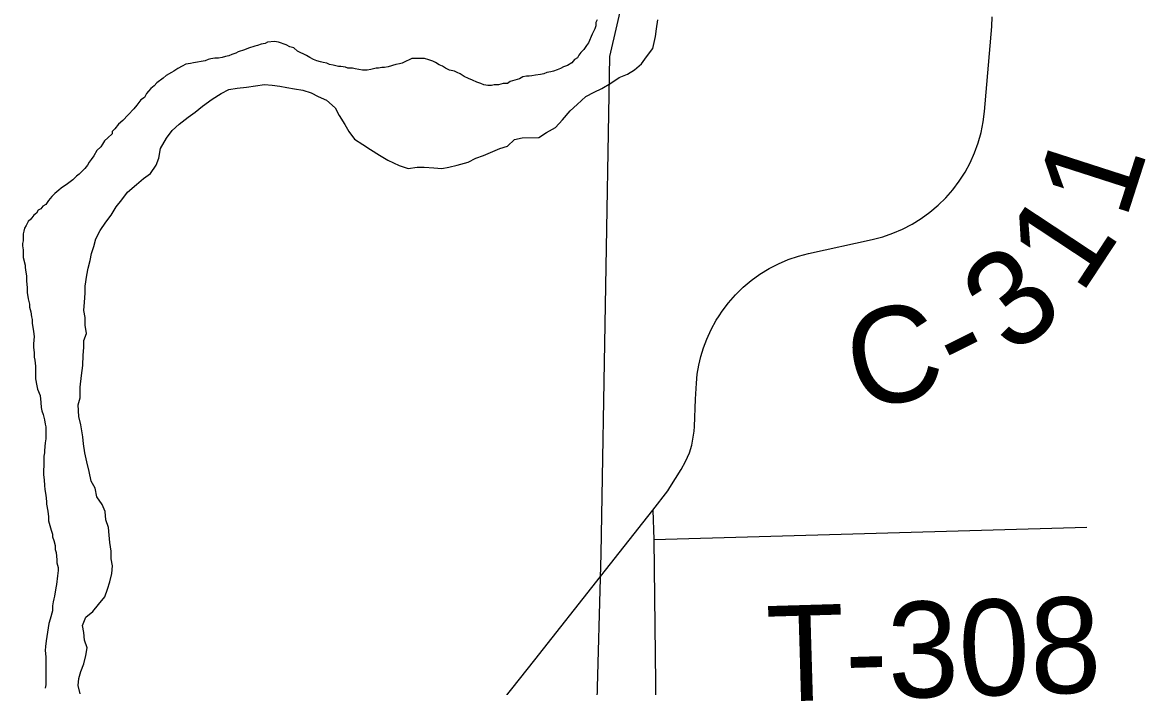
# Model space of a CAD drawing. Extents: x -59 to 82, y -3 to 49.
# Drawn here: x -52.911 to -52.245, y 46.56 to 46.954 of the extents above; entities that cross this region are included whole.
import ezdxf

# ---------------------------------------------------------------- set-up
doc = ezdxf.new("R2010")
doc.units = 0
for name, color, linetype in [('GM_X_Corporation', 7, 'Continuous'), ('GM_X_County_Road', 7, 'Continuous'), ('GM_X_County_Road_Text', 7, 'Continuous'), ('GM_X_Major_River', 7, 'Continuous'), ('GM_X_Township_Road', 7, 'Continuous'), ('GM_X_Township_Road_Text', 7, 'Continuous')]:
    doc.layers.add(name, color=color, linetype=linetype)

msp = doc.modelspace()

# ---------------------------------------------------------------- linework, layer by layer
at = {"layer": 'GM_X_Corporation'}
for p, q in [((-52.56251, 46.93385), (-52.55268, 46.97631)), ((-52.56755, 46.63881), (-52.56251, 46.93385)), ((-52.57812, 46.27168), (-52.56755, 46.63881))]:
    msp.add_line(p, q, dxfattribs=at)
at = {"layer": 'GM_X_County_Road'}
for p, q in [((-52.34011, 46.90124), (-52.33576, 46.95155)), ((-52.33576, 46.95155), (-52.3355, 46.95721)), ((-52.34089, 46.89493), (-52.34011, 46.90124)), ((-52.34214, 46.8887), (-52.34089, 46.89493)), ((-52.34385, 46.88258), (-52.34214, 46.8887)), ((-52.34602, 46.8766), (-52.34385, 46.88258)), ((-52.34862, 46.8708), (-52.34602, 46.8766)), ((-52.35508, 46.85986), (-52.35164, 46.86521)), ((-52.35164, 46.86521), (-52.34862, 46.8708)), ((-52.3589, 46.85478), (-52.35508, 46.85986)), ((-52.36309, 46.85), (-52.3589, 46.85478)), ((-52.37248, 46.84144), (-52.36763, 46.84554)), ((-52.36763, 46.84554), (-52.36309, 46.85)), ((-52.38304, 46.83437), (-52.37763, 46.83771)), ((-52.37763, 46.83771), (-52.37248, 46.84144)), ((-52.39453, 46.82895), (-52.38868, 46.83144)), ((-52.38868, 46.83144), (-52.38304, 46.83437)), ((-52.44447, 46.81695), (-52.4067, 46.82529)), ((-52.4067, 46.82529), (-52.40054, 46.82689)), ((-52.40054, 46.82689), (-52.39453, 46.82895)), ((-52.46238, 46.81085), (-52.45657, 46.81332)), ((-52.45657, 46.81332), (-52.45059, 46.81536)), ((-52.45059, 46.81536), (-52.44447, 46.81695)), ((-52.4785, 46.80095), (-52.47338, 46.80464)), ((-52.47338, 46.80464), (-52.468, 46.80795)), ((-52.468, 46.80795), (-52.46238, 46.81085)), ((-52.48334, 46.79688), (-52.4785, 46.80095)), ((-52.49205, 46.78774), (-52.48786, 46.79247)), ((-52.48786, 46.79247), (-52.48334, 46.79688)), ((-52.49587, 46.78271), (-52.49205, 46.78774)), ((-52.49931, 46.77741), (-52.49759, 46.78006)), ((-52.49759, 46.78006), (-52.49587, 46.78271)), ((-52.50496, 46.76612), (-52.50234, 46.77187)), ((-52.50234, 46.77187), (-52.49931, 46.77741)), ((-52.50685, 46.76109), (-52.50496, 46.76612)), ((-52.50841, 46.75595), (-52.50685, 46.76109)), ((-52.50965, 46.75073), (-52.50841, 46.75595)), ((-52.51113, 46.7401), (-52.51056, 46.74544)), ((-52.51056, 46.74544), (-52.50965, 46.75073)), ((-52.51154, 46.7306), (-52.51113, 46.7401)), ((-52.51215, 46.71433), (-52.51154, 46.7306)), ((-52.51376, 46.70335), (-52.51238, 46.71154)), ((-52.51238, 46.71154), (-52.51215, 46.71433)), ((-52.51751, 46.69351), (-52.51514, 46.69875)), ((-52.51514, 46.69875), (-52.51376, 46.70335)), ((-52.52007, 46.68875), (-52.51751, 46.69351)), ((-52.52685, 46.67809), (-52.52007, 46.68875)), ((-52.52809, 46.67616), (-52.52685, 46.67809)), ((-52.537, 46.66472), (-52.52809, 46.67616)), ((-52.56795, 46.62544), (-52.537, 46.66472)), ((-52.537, 46.66472), (-52.53639, 46.64724)), ((-52.53639, 46.64724), (-52.53288, 46.33389)), ((-52.60695, 46.57594), (-52.56795, 46.62544)), ((-52.6297, 46.54725), (-52.60695, 46.57594))]:
    msp.add_line(p, q, dxfattribs=at)
at = {"layer": 'GM_X_Major_River'}
for p, q in [((-52.5707, 46.95203), (-52.57145, 46.95014)), ((-52.56995, 46.95545), (-52.57071, 46.95393)), ((-52.57071, 46.95393), (-52.5707, 46.95203)), ((-52.53473, 46.9502), (-52.53399, 46.95551)), ((-52.57296, 46.9471), (-52.57522, 46.94179)), ((-52.57145, 46.95014), (-52.57296, 46.9471)), ((-52.53698, 46.93845), (-52.53548, 46.94565)), ((-52.53548, 46.94565), (-52.53473, 46.9502)), ((-52.77926, 46.93765), (-52.78305, 46.93651)), ((-52.77699, 46.93879), (-52.77926, 46.93765)), ((-52.77321, 46.93993), (-52.77699, 46.93879)), ((-52.7717, 46.94032), (-52.77321, 46.93993)), ((-52.76943, 46.94108), (-52.7717, 46.94032)), ((-52.76716, 46.94146), (-52.76943, 46.94108)), ((-52.76564, 46.94222), (-52.76716, 46.94146)), ((-52.76148, 46.94261), (-52.76564, 46.94222)), ((-52.75921, 46.94223), (-52.76148, 46.94261)), ((-52.75466, 46.94072), (-52.75921, 46.94223)), ((-52.75239, 46.93959), (-52.75466, 46.94072)), ((-52.75011, 46.93884), (-52.75239, 46.93959)), ((-52.74784, 46.93695), (-52.75011, 46.93884)), ((-52.57786, 46.938), (-52.57975, 46.9361)), ((-52.57635, 46.94027), (-52.57786, 46.938)), ((-52.57522, 46.94179), (-52.57635, 46.94027)), ((-52.54075, 46.93351), (-52.53698, 46.93845)), ((-52.80272, 46.93117), (-52.80953, 46.93002)), ((-52.80083, 46.93193), (-52.80272, 46.93117)), ((-52.79931, 46.93231), (-52.80083, 46.93193)), ((-52.79704, 46.93269), (-52.79931, 46.93231)), ((-52.79477, 46.9327), (-52.79704, 46.93269)), ((-52.7925, 46.93308), (-52.79477, 46.9327)), ((-52.79061, 46.93384), (-52.7925, 46.93308)), ((-52.78872, 46.93422), (-52.79061, 46.93384)), ((-52.78683, 46.93499), (-52.78872, 46.93422)), ((-52.78456, 46.93574), (-52.78683, 46.93499)), ((-52.78305, 46.93651), (-52.78456, 46.93574)), ((-52.74632, 46.93619), (-52.74784, 46.93695)), ((-52.74405, 46.93506), (-52.74632, 46.93619)), ((-52.74253, 46.9343), (-52.74405, 46.93506)), ((-52.74064, 46.93317), (-52.74253, 46.9343)), ((-52.73836, 46.93203), (-52.74064, 46.93317)), ((-52.73647, 46.93128), (-52.73836, 46.93203)), ((-52.7342, 46.93052), (-52.73647, 46.93128)), ((-52.68347, 46.93099), (-52.68574, 46.92985)), ((-52.68158, 46.93175), (-52.68347, 46.93099)), ((-52.68007, 46.93251), (-52.68158, 46.93175)), ((-52.67249, 46.93253), (-52.68007, 46.93251)), ((-52.66984, 46.93177), (-52.67249, 46.93253)), ((-52.66757, 46.93102), (-52.66984, 46.93177)), ((-52.66605, 46.93026), (-52.66757, 46.93102)), ((-52.58353, 46.93192), (-52.58504, 46.93002)), ((-52.58164, 46.93306), (-52.58353, 46.93192)), ((-52.58088, 46.93458), (-52.58164, 46.93306)), ((-52.57975, 46.9361), (-52.58088, 46.93458)), ((-52.54377, 46.92934), (-52.54075, 46.93351)), ((-52.82277, 46.92431), (-52.82579, 46.92241)), ((-52.82126, 46.92507), (-52.82277, 46.92431)), ((-52.81899, 46.92659), (-52.82126, 46.92507)), ((-52.81634, 46.92811), (-52.81899, 46.92659)), ((-52.81407, 46.92925), (-52.81634, 46.92811)), ((-52.81142, 46.92963), (-52.81407, 46.92925)), ((-52.80953, 46.93002), (-52.81142, 46.92963)), ((-52.73268, 46.93015), (-52.7342, 46.93052)), ((-52.73041, 46.92977), (-52.73268, 46.93015)), ((-52.7289, 46.92902), (-52.73041, 46.92977)), ((-52.72662, 46.92864), (-52.7289, 46.92902)), ((-52.72359, 46.92789), (-52.72662, 46.92864)), ((-52.72208, 46.92789), (-52.72359, 46.92789)), ((-52.71943, 46.92752), (-52.72208, 46.92789)), ((-52.71791, 46.92676), (-52.71943, 46.92752)), ((-52.71526, 46.92677), (-52.71791, 46.92676)), ((-52.71375, 46.92639), (-52.71526, 46.92677)), ((-52.7092, 46.92564), (-52.71375, 46.92639)), ((-52.70655, 46.92565), (-52.7092, 46.92564)), ((-52.70428, 46.92603), (-52.70655, 46.92565)), ((-52.70125, 46.92679), (-52.70428, 46.92603)), ((-52.69974, 46.92679), (-52.70125, 46.92679)), ((-52.69785, 46.92717), (-52.69974, 46.92679)), ((-52.69633, 46.92718), (-52.69785, 46.92717)), ((-52.69406, 46.92756), (-52.69633, 46.92718)), ((-52.68952, 46.92909), (-52.69406, 46.92756)), ((-52.68725, 46.92947), (-52.68952, 46.92909)), ((-52.68574, 46.92985), (-52.68725, 46.92947)), ((-52.66378, 46.92875), (-52.66605, 46.93026)), ((-52.66188, 46.928), (-52.66378, 46.92875)), ((-52.65999, 46.92686), (-52.66188, 46.928)), ((-52.65772, 46.92573), (-52.65999, 46.92686)), ((-52.65468, 46.92498), (-52.65772, 46.92573)), ((-52.65317, 46.92422), (-52.65468, 46.92498)), ((-52.65127, 46.92347), (-52.65317, 46.92422)), ((-52.59979, 46.92431), (-52.60168, 46.92355)), ((-52.59752, 46.9247), (-52.59979, 46.92431)), ((-52.59601, 46.92508), (-52.59752, 46.9247)), ((-52.59374, 46.92584), (-52.59601, 46.92508)), ((-52.59185, 46.9266), (-52.59374, 46.92584)), ((-52.58996, 46.92774), (-52.59185, 46.9266)), ((-52.58769, 46.9285), (-52.58996, 46.92774)), ((-52.58504, 46.93002), (-52.58769, 46.9285)), ((-52.55209, 46.92326), (-52.54793, 46.92592)), ((-52.54793, 46.92592), (-52.54377, 46.92934)), ((-52.83146, 46.91823), (-52.83297, 46.91633)), ((-52.82768, 46.92089), (-52.83146, 46.91823)), ((-52.82579, 46.92241), (-52.82768, 46.92089)), ((-52.649, 46.92195), (-52.65127, 46.92347)), ((-52.64635, 46.92082), (-52.649, 46.92195)), ((-52.64407, 46.91969), (-52.64635, 46.92082)), ((-52.64142, 46.91856), (-52.64407, 46.91969)), ((-52.63915, 46.9178), (-52.64142, 46.91856)), ((-52.63725, 46.91705), (-52.63915, 46.9178)), ((-52.6259, 46.91782), (-52.62855, 46.91706)), ((-52.62325, 46.91783), (-52.6259, 46.91782)), ((-52.62174, 46.91897), (-52.62325, 46.91783)), ((-52.62022, 46.91935), (-52.62174, 46.91897)), ((-52.61758, 46.92011), (-52.62022, 46.91935)), ((-52.61606, 46.92049), (-52.61758, 46.92011)), ((-52.61417, 46.92163), (-52.61606, 46.92049)), ((-52.6119, 46.92202), (-52.61417, 46.92163)), ((-52.61039, 46.92202), (-52.6119, 46.92202)), ((-52.60887, 46.9224), (-52.61039, 46.92202)), ((-52.6066, 46.92278), (-52.60887, 46.9224)), ((-52.60357, 46.92317), (-52.6066, 46.92278)), ((-52.60168, 46.92355), (-52.60357, 46.92317)), ((-52.56721, 46.91489), (-52.56192, 46.91793)), ((-52.56192, 46.91793), (-52.55701, 46.92135)), ((-52.55701, 46.92135), (-52.55209, 46.92326)), ((-52.83751, 46.91177), (-52.83864, 46.9095)), ((-52.83637, 46.91329), (-52.83751, 46.91177)), ((-52.83486, 46.91481), (-52.83637, 46.91329)), ((-52.83297, 46.91633), (-52.83486, 46.91481)), ((-52.79851, 46.90843), (-52.79322, 46.91185)), ((-52.79322, 46.91185), (-52.78868, 46.91413)), ((-52.78868, 46.91413), (-52.78376, 46.9149)), ((-52.78376, 46.9149), (-52.77808, 46.91567)), ((-52.77808, 46.91567), (-52.76748, 46.9172)), ((-52.76748, 46.9172), (-52.76294, 46.91683)), ((-52.76294, 46.91683), (-52.7584, 46.91608)), ((-52.7584, 46.91608), (-52.75423, 46.91533)), ((-52.75423, 46.91533), (-52.74968, 46.91458)), ((-52.74968, 46.91458), (-52.74476, 46.91383)), ((-52.74476, 46.91383), (-52.73984, 46.91232)), ((-52.73984, 46.91232), (-52.73567, 46.91005)), ((-52.63498, 46.91667), (-52.63725, 46.91705)), ((-52.63271, 46.91667), (-52.63498, 46.91667)), ((-52.6312, 46.91706), (-52.63271, 46.91667)), ((-52.62855, 46.91706), (-52.6312, 46.91706)), ((-52.57667, 46.90995), (-52.57175, 46.91261)), ((-52.57175, 46.91261), (-52.56721, 46.91489)), ((-52.84317, 46.90494), (-52.84506, 46.90266)), ((-52.84091, 46.90798), (-52.84317, 46.90494)), ((-52.83864, 46.9095), (-52.84091, 46.90798)), ((-52.80871, 46.90083), (-52.80418, 46.90425)), ((-52.80418, 46.90425), (-52.79851, 46.90843)), ((-52.73567, 46.91005), (-52.73074, 46.90779)), ((-52.73074, 46.90779), (-52.72543, 46.90325)), ((-52.58611, 46.90159), (-52.58196, 46.90539)), ((-52.58196, 46.90539), (-52.57667, 46.90995)), ((-52.84846, 46.89925), (-52.85148, 46.89583)), ((-52.84506, 46.90266), (-52.84846, 46.89925)), ((-52.81816, 46.89361), (-52.81287, 46.89779)), ((-52.81287, 46.89779), (-52.80871, 46.90083)), ((-52.72543, 46.90325), (-52.72315, 46.8987)), ((-52.72315, 46.8987), (-52.71973, 46.8934)), ((-52.59064, 46.89628), (-52.58611, 46.90159)), ((-52.85639, 46.89089), (-52.8579, 46.88937)), ((-52.85412, 46.89355), (-52.85639, 46.89089)), ((-52.85148, 46.89583), (-52.85412, 46.89355)), ((-52.82232, 46.88981), (-52.81816, 46.89361)), ((-52.71973, 46.8934), (-52.71745, 46.88924)), ((-52.60009, 46.88868), (-52.5948, 46.89172)), ((-52.5948, 46.89172), (-52.59064, 46.89628)), ((-52.86054, 46.88558), (-52.86243, 46.88368)), ((-52.8579, 46.88786), (-52.86054, 46.88558)), ((-52.8579, 46.88937), (-52.8579, 46.88786)), ((-52.82911, 46.87919), (-52.82571, 46.88526)), ((-52.82571, 46.88526), (-52.82232, 46.88981)), ((-52.71745, 46.88924), (-52.71403, 46.88469)), ((-52.71403, 46.88469), (-52.70911, 46.88167)), ((-52.62317, 46.88068), (-52.61901, 46.88448)), ((-52.61901, 46.88448), (-52.61447, 46.88562)), ((-52.61447, 46.88562), (-52.60463, 46.88564)), ((-52.60463, 46.88564), (-52.60009, 46.88868)), ((-52.86696, 46.87799), (-52.86885, 46.87495)), ((-52.8647, 46.88026), (-52.86696, 46.87799)), ((-52.86356, 46.88178), (-52.8647, 46.88026)), ((-52.86243, 46.88368), (-52.86356, 46.88178)), ((-52.83023, 46.8735), (-52.82911, 46.87919)), ((-52.70911, 46.88167), (-52.70456, 46.87864)), ((-52.70456, 46.87864), (-52.69925, 46.87524)), ((-52.63338, 46.87687), (-52.62771, 46.87916)), ((-52.62771, 46.87916), (-52.62317, 46.88068)), ((-52.87149, 46.87116), (-52.87262, 46.86926)), ((-52.87036, 46.87267), (-52.87149, 46.87116)), ((-52.86885, 46.87495), (-52.87036, 46.87267)), ((-52.83174, 46.86933), (-52.83023, 46.8735)), ((-52.69925, 46.87524), (-52.69432, 46.87222)), ((-52.69432, 46.87222), (-52.6875, 46.8692)), ((-52.65305, 46.86926), (-52.64662, 46.87117)), ((-52.64662, 46.87117), (-52.64208, 46.87345)), ((-52.64208, 46.87345), (-52.63754, 46.87497)), ((-52.63754, 46.87497), (-52.63338, 46.87687)), ((-52.87413, 46.86736), (-52.87753, 46.86394)), ((-52.87262, 46.86926), (-52.87413, 46.86736)), ((-52.83929, 46.86135), (-52.83513, 46.86439)), ((-52.83513, 46.86439), (-52.83174, 46.86933)), ((-52.6875, 46.8692), (-52.6822, 46.86731)), ((-52.6822, 46.86731), (-52.6769, 46.86808)), ((-52.6769, 46.86808), (-52.67273, 46.86809)), ((-52.67273, 46.86809), (-52.66705, 46.86772)), ((-52.66705, 46.86772), (-52.66213, 46.86735)), ((-52.66213, 46.86735), (-52.65797, 46.86811)), ((-52.65797, 46.86811), (-52.65305, 46.86926)), ((-52.88433, 46.85825), (-52.88811, 46.85559)), ((-52.88131, 46.86053), (-52.88433, 46.85825)), ((-52.87904, 46.8628), (-52.88131, 46.86053)), ((-52.87753, 46.86394), (-52.87904, 46.8628)), ((-52.84874, 46.85338), (-52.84345, 46.85794)), ((-52.84345, 46.85794), (-52.83929, 46.86135)), ((-52.89189, 46.85255), (-52.89378, 46.85065)), ((-52.88963, 46.85445), (-52.89189, 46.85255)), ((-52.88811, 46.85559), (-52.88963, 46.85445)), ((-52.85214, 46.84883), (-52.84874, 46.85338)), ((-52.89907, 46.84495), (-52.9002, 46.84344)), ((-52.89718, 46.84609), (-52.89907, 46.84495)), ((-52.89567, 46.84837), (-52.89718, 46.84609)), ((-52.89378, 46.85065), (-52.89567, 46.84837)), ((-52.85855, 46.83972), (-52.85553, 46.84465)), ((-52.85553, 46.84465), (-52.85214, 46.84883)), ((-52.90436, 46.83964), (-52.90625, 46.83736)), ((-52.90285, 46.84078), (-52.90436, 46.83964)), ((-52.90172, 46.84267), (-52.90285, 46.84078)), ((-52.9002, 46.84344), (-52.90172, 46.84267)), ((-52.86157, 46.83554), (-52.85855, 46.83972)), ((-52.91002, 46.83205), (-52.9104, 46.83015)), ((-52.90889, 46.83356), (-52.91002, 46.83205)), ((-52.90776, 46.83584), (-52.90889, 46.83356)), ((-52.90625, 46.83736), (-52.90776, 46.83584)), ((-52.86497, 46.83061), (-52.86157, 46.83554)), ((-52.91076, 46.82447), (-52.91114, 46.82295)), ((-52.9104, 46.83015), (-52.91077, 46.82863)), ((-52.91077, 46.82863), (-52.91076, 46.82447)), ((-52.86873, 46.82113), (-52.86761, 46.82568)), ((-52.86761, 46.82568), (-52.86497, 46.83061)), ((-52.91114, 46.82295), (-52.91113, 46.82143)), ((-52.91113, 46.82143), (-52.91075, 46.81916)), ((-52.91075, 46.81916), (-52.91074, 46.81461)), ((-52.87024, 46.81695), (-52.86873, 46.82113)), ((-52.91074, 46.81461), (-52.90959, 46.81006)), ((-52.87211, 46.80823), (-52.87099, 46.81278)), ((-52.87099, 46.81278), (-52.87024, 46.81695)), ((-52.90959, 46.81006), (-52.90959, 46.80855)), ((-52.90959, 46.80855), (-52.90921, 46.80589)), ((-52.90921, 46.80589), (-52.90883, 46.80362)), ((-52.87286, 46.80406), (-52.87211, 46.80823)), ((-52.90883, 46.80362), (-52.90882, 46.80059)), ((-52.90882, 46.80059), (-52.90843, 46.7968)), ((-52.87398, 46.79761), (-52.87286, 46.80406)), ((-52.87397, 46.79345), (-52.87398, 46.79761)), ((-52.90843, 46.7968), (-52.90842, 46.79376)), ((-52.90842, 46.79376), (-52.90766, 46.78998)), ((-52.87434, 46.78814), (-52.87397, 46.79345)), ((-52.90766, 46.78998), (-52.9069, 46.78694)), ((-52.9069, 46.78694), (-52.90689, 46.78505)), ((-52.90689, 46.78505), (-52.90613, 46.7824)), ((-52.87471, 46.78321), (-52.87434, 46.78814)), ((-52.90613, 46.7824), (-52.90574, 46.77937)), ((-52.90574, 46.77937), (-52.90536, 46.77785)), ((-52.90536, 46.77785), (-52.90536, 46.77558)), ((-52.87394, 46.77904), (-52.87471, 46.78321)), ((-52.87393, 46.77449), (-52.87394, 46.77904)), ((-52.90536, 46.77558), (-52.90459, 46.77065)), ((-52.87316, 46.76957), (-52.87393, 46.77449)), ((-52.90459, 46.77065), (-52.9042, 46.76762)), ((-52.9042, 46.76762), (-52.90457, 46.76345)), ((-52.87467, 46.76539), (-52.87316, 46.76957)), ((-52.87466, 46.76122), (-52.87467, 46.76539)), ((-52.90457, 46.76345), (-52.90457, 46.76117)), ((-52.90457, 46.76117), (-52.90418, 46.75814)), ((-52.90418, 46.75814), (-52.90418, 46.75549)), ((-52.87503, 46.75667), (-52.87466, 46.76122)), ((-52.90418, 46.75549), (-52.90379, 46.75359)), ((-52.90379, 46.75359), (-52.90341, 46.75018)), ((-52.8754, 46.75061), (-52.87503, 46.75667)), ((-52.90341, 46.75018), (-52.90339, 46.7426)), ((-52.87688, 46.73772), (-52.87614, 46.74454)), ((-52.87614, 46.74454), (-52.8754, 46.75061)), ((-52.90339, 46.7426), (-52.90263, 46.73843)), ((-52.90263, 46.73843), (-52.90224, 46.73654)), ((-52.87687, 46.73127), (-52.87688, 46.73772)), ((-52.90224, 46.73654), (-52.90072, 46.73275)), ((-52.90072, 46.73275), (-52.90033, 46.72858)), ((-52.87799, 46.7271), (-52.87687, 46.73127)), ((-52.90033, 46.72858), (-52.89995, 46.72555)), ((-52.89995, 46.72555), (-52.89957, 46.72365)), ((-52.8776, 46.72028), (-52.87799, 46.7271)), ((-52.89957, 46.72365), (-52.8988, 46.72138)), ((-52.8988, 46.72138), (-52.89804, 46.71835)), ((-52.89804, 46.71835), (-52.89766, 46.7157)), ((-52.87646, 46.71535), (-52.8776, 46.72028)), ((-52.89766, 46.7157), (-52.89727, 46.71418)), ((-52.89727, 46.71418), (-52.89726, 46.70698)), ((-52.8753, 46.70815), (-52.87646, 46.71535)), ((-52.89763, 46.7047), (-52.898, 46.70016)), ((-52.89726, 46.70698), (-52.89763, 46.7047)), ((-52.87492, 46.70399), (-52.8753, 46.70815)), ((-52.898, 46.69864), (-52.89837, 46.69674)), ((-52.898, 46.70016), (-52.898, 46.69864)), ((-52.87415, 46.69868), (-52.87492, 46.70399)), ((-52.873, 46.69338), (-52.87415, 46.69868)), ((-52.89837, 46.69674), (-52.89836, 46.69257)), ((-52.89836, 46.69257), (-52.89836, 46.69068)), ((-52.87147, 46.68769), (-52.873, 46.69338)), ((-52.89836, 46.69068), (-52.89873, 46.68878)), ((-52.89873, 46.68878), (-52.89873, 46.68575)), ((-52.89873, 46.68575), (-52.89834, 46.68272)), ((-52.87033, 46.68201), (-52.87147, 46.68769)), ((-52.89834, 46.68272), (-52.89796, 46.67931)), ((-52.89796, 46.67931), (-52.89795, 46.67703)), ((-52.86804, 46.67784), (-52.87033, 46.68201)), ((-52.8669, 46.67254), (-52.86804, 46.67784)), ((-52.89795, 46.67703), (-52.89719, 46.67362)), ((-52.89719, 46.67362), (-52.8968, 46.66983)), ((-52.86386, 46.66799), (-52.8669, 46.67254)), ((-52.8968, 46.66983), (-52.8968, 46.66831)), ((-52.8968, 46.66831), (-52.89603, 46.66415)), ((-52.86196, 46.66383), (-52.86386, 46.66799)), ((-52.89603, 46.66415), (-52.89565, 46.66074)), ((-52.89565, 46.66074), (-52.89564, 46.65846)), ((-52.89564, 46.65846), (-52.89411, 46.65278)), ((-52.86157, 46.6589), (-52.86196, 46.66383)), ((-52.86005, 46.65435), (-52.86157, 46.6589)), ((-52.89411, 46.65278), (-52.89335, 46.65051)), ((-52.85966, 46.64981), (-52.86005, 46.65435)), ((-52.89335, 46.65051), (-52.89335, 46.64899)), ((-52.89335, 46.64899), (-52.89259, 46.64672)), ((-52.89259, 46.64672), (-52.89182, 46.64369)), ((-52.85927, 46.64564), (-52.85966, 46.64981)), ((-52.8585, 46.64033), (-52.85927, 46.64564)), ((-52.89182, 46.64369), (-52.89182, 46.64141)), ((-52.89182, 46.64141), (-52.89106, 46.63952)), ((-52.89106, 46.63952), (-52.89067, 46.63535)), ((-52.85849, 46.63578), (-52.8585, 46.64033)), ((-52.89067, 46.63535), (-52.89066, 46.63345)), ((-52.89066, 46.63345), (-52.8899, 46.6308)), ((-52.85772, 46.63161), (-52.85849, 46.63578)), ((-52.85809, 46.62706), (-52.85772, 46.63161)), ((-52.89027, 46.62587), (-52.89101, 46.62056)), ((-52.8899, 46.62891), (-52.89027, 46.62587)), ((-52.8899, 46.6308), (-52.8899, 46.62891)), ((-52.85922, 46.62213), (-52.85809, 46.62706)), ((-52.89139, 46.61867), (-52.89214, 46.61374)), ((-52.89101, 46.62056), (-52.89139, 46.61867)), ((-52.86223, 46.61341), (-52.86072, 46.61796)), ((-52.86072, 46.61796), (-52.85922, 46.62213)), ((-52.89251, 46.61222), (-52.89289, 46.61033)), ((-52.89214, 46.61374), (-52.89251, 46.61222)), ((-52.86601, 46.60886), (-52.86223, 46.61341)), ((-52.89325, 46.60502), (-52.89476, 46.60009)), ((-52.89289, 46.61033), (-52.89326, 46.60805)), ((-52.89326, 46.60805), (-52.89325, 46.60502)), ((-52.87356, 46.60126), (-52.8694, 46.60468)), ((-52.8694, 46.60468), (-52.86601, 46.60886)), ((-52.89476, 46.60009), (-52.89551, 46.59743)), ((-52.87544, 46.59633), (-52.87356, 46.60126)), ((-52.89551, 46.59743), (-52.89663, 46.58985)), ((-52.87468, 46.59216), (-52.87544, 46.59633)), ((-52.87429, 46.58762), (-52.87468, 46.59216)), ((-52.897, 46.5872), (-52.89737, 46.58378)), ((-52.89663, 46.58985), (-52.897, 46.5872)), ((-52.87276, 46.58307), (-52.87429, 46.58762)), ((-52.89737, 46.58378), (-52.89775, 46.58151)), ((-52.89775, 46.58151), (-52.89736, 46.57772)), ((-52.89736, 46.57772), (-52.89733, 46.56635)), ((-52.87464, 46.57359), (-52.87351, 46.57852)), ((-52.87351, 46.57852), (-52.87276, 46.58307)), ((-52.87652, 46.56904), (-52.87464, 46.57359)), ((-52.89733, 46.56635), (-52.89733, 46.56445)), ((-52.89733, 46.56445), (-52.89732, 46.56104)), ((-52.87802, 46.5607), (-52.87765, 46.56487)), ((-52.87765, 46.56487), (-52.87652, 46.56904)), ((-52.89732, 46.56104), (-52.8977, 46.55914)), ((-52.87687, 46.55577), (-52.87802, 46.5607))]:
    msp.add_line(p, q, dxfattribs=at)
at = {"layer": 'GM_X_Township_Road'}
msp.add_line((-52.53639, 46.64724), (-52.27941, 46.65458), dxfattribs=at)

# ---------------------------------------------------------------- texts
at = {"layer": 'GM_X_County_Road_Text'}
for s, rotation, p in [('1', 72.14012, (-52.25633, 46.8361)), ('1', 56.58584, (-52.28287, 46.79174)), ('3', 38.24109, (-52.32375, 46.75551)), ('C', 13.011, (-52.41458, 46.72295)), ('-', 26.27441, (-52.35561, 46.73828))]:
    msp.add_text(s, height=0.05682, rotation=rotation, dxfattribs=at).set_placement(p)
at = {"layer": 'GM_X_Township_Road_Text'}
msp.add_text('T-308', height=0.056818, rotation=1.68374, dxfattribs=at).set_placement((-52.46861, 46.55099))

doc.saveas('drawing.dxf')
